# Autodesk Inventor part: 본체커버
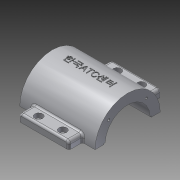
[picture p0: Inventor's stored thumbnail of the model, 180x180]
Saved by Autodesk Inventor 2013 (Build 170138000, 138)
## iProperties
Created: 2015-12
Part Number: 본체커버
Material: 알루미늄 6061
Document SubType Name: Modeling
Designer: mduedu
Density: 2.40731 g/cm^3
Mass: 177.082 g
Surface Area: 200.806 cm^2
Volume: 73.5601 cm^3
Author: mduedu
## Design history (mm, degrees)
sketch "스케치1"
  geometry: L1 (45, 40)-(-45, 40); L2 (-45, 40)-(-45, -40); L3 (-45, -40)-(45, -40); L4 (45, -40)-(45, 40); L5 (45, 40)-(-45, -40); L6 (-45, 40)-(45, -40); 1 further point
  constraints: 12 end point, 2 midpoint, 2 parallel, 1 horizontal, 1 perpendicular
  dimensions: "d0" = 90 distance of L2.end L3.end; "d2" = 80 distance of L1.end L2.end
extrude "돌출1" new body sketch "스케치1" distance "d3" = 10; taper "d4" = 0 deg
sketch "스케치2"
  geometry: L1 (0, 40)-(0, -40) reference; C1 r 32.5 at (80, 0); 1 further point
  constraints: 1 centre point
  dimensions: "d5" = 65 diameter of C1; "d6" = 80 distance from line of C1.centre L1
extrude "돌출2" join sketch "스케치2" stored distance "d7" = 75; taper "d8" = 0 deg
sketch "스케치3"
  geometry: L1 (-27.5, -20)-(27.5, -20); L2 (27.5, -20)-(27.5, 20); L3 (27.5, 20)-(-27.5, 20); L4 (-27.5, 20)-(-27.5, -20); L5 (-27.5, -20)-(27.5, 20); L6 (27.5, -20)-(-27.5, 20); 1 further point
  constraints: 12 end point, 2 midpoint, 2 parallel, 1 horizontal, 1 perpendicular
  dimensions: "d9" = 55 distance of L2.end L3.end; "d11" = 40 distance of L1.end L2.end
extrude "돌출3" new body sketch "스케치3" stored distance "d12" = 75; taper "d13" = 0 deg
fillet "모깎기1"
fillet "모깎기2"
feature "결합1"
  node "솔리드2"
fillet "모깎기3" dims "d14" = 10
sketch "스케치4"
  geometry: L1 (-37.5, 47.5)-(37.5, 47.5) reference; L2 (35, 10)-(45, 10) reference; L3 (32.5, 47.5)-(40, 10); L4 (37.5, 47.5)-(37.5, 112.5) reference; L5 (45, 10)-(45, 0) reference; 1 further point
  constraints: 2 end point, 1 midpoint, 1 point on line
  dimensions: "d15" = 5 distance from line of L3.start L4; "d16" = 5 distance from line of L3.end L5
sketch "스케치5"
  geometry: L1 (10, 40)-(10, 30) reference; L2 (10, 35)-(56.569, 22.522); L3 (0, 40)-(10, 40) reference; 2 further points
  constraints: 2 end point, 1 midpoint, 2 other
  dimensions: "d17" = 5 distance from line of L2.start L3; "d18" = 15 deg angle of L2 L3
feature "리브1" dims "d19" = 1, "d20" = 6, "d21" = 0, "d22" = 0, "d23" = 1, "d24" = 1
feature "리브2" dims "d25" = 1, "d26" = 6, "d27" = 0, "d28" = 0, "d29" = 1, "d30" = 1
fillet "모깎기4" dims "d31" = 2
fillet "모깎기5" dims "d32" = 2
fillet "모깎기6" dims "d33" = 2
sketch "스케치6"
  geometry: A1 r 10 centre (-35, 30) between (-35, 40) and (-45, 30) reference; A2 r 10 centre (35, 30) between (45, 30) and (35, 40) reference; A3 r 10 centre (35, -30) between (35, -40) and (45, -30) reference; A4 r 10 centre (-35, -30) between (-45, -30) and (-35, -40) reference; 5 further points
  constraints: 4 coincident
hole "구멍1" sketch "스케치6" at (-35, 30), (35, 30), (35, -30), (-35, -30) diameter "d34" = 7; stored, may be unused: countersink angle "d38" = 90 deg, drill point angle "d40" = 118 deg; dims "d35" = 6, "d36" = 12, "d37" = 3, "d39" = 8
fillet "모깎기7" dims "d41" = 2
hole "구멍2" diameter "d44" = 45; stored, may be unused: countersink angle "d48" = 90 deg, drill point angle "d50" = 118 deg; dims "d42" = 10, "d43" = 10, "d45" = 6, "d46" = 4, "d47" = 2, "d49" = 8
sketch "스케치7" dims "d52" = 26.5
  geometry: L1 (0, 0)-(32.5, 0); L2 (0, 0)-(22.981, 22.981); A1 r 32.5 centre (0, 0) between (32.5, 0) and (22.981, 22.981) reference; 3 further points
  constraints: 4 end point, 2 point on circle, 1 coincident, 1 horizontal, 1 point on line, 3 other
  dimensions: "d51" = 45 deg angle of L2 L1
hole "구멍3" sketch "스케치7" at (18.738, 18.738) diameter "d54" = 2.459; stored, may be unused: countersink angle "d58" = 90 deg, drill point angle "d60" = 118 deg; dims "d55" = 8, "d56" = 4, "d57" = 2, "d59" = 10
sketch "스케치8"
  geometry: L1 (72.5, 31.623)-(72.5, 46); L2 (72.5, 46)-(87.5, 46); L3 (87.5, 46)-(87.5, 31.623); A1 r 32.5 centre (80, 0) between (87.5, 31.623) and (72.5, 31.623) reference; 2 further points
  constraints: 6 end point, 2 point on circle, 1 midpoint, 1 parallel, 1 vertical, 1 vertical alignment
  dimensions: "d64" = 15 distance of L1.end L2.end; "d66" = 46 distance from line of L2 A1.centre
extrude "돌출4" join sketch "스케치8" stored distance "d67" = 50; taper "d68" = 0 deg
fillet "모깎기8" dims "d69" = 3
fillet "모깎기9" dims "d70" = 2
sketch "스케치13"
  geometry: L1 (-46, 80)-(106, 80); L2 (106, 80)-(106, -30); L3 (106, -30)-(-46, -30); L4 (-46, -30)-(-46, 80); L5 (0, 0)-(60, 0) reference; L6 (76, 75.5)-(76, 84.5) reference; C1 r 32.5 at (30, 80) reference; 1 further point
  constraints: 8 end point, 2 parallel, 1 coincident, 1 horizontal, 1 midpoint, 1 perpendicular
  dimensions: "d99" = 30 distance between parallel lines of L3 L5; "d100" = 30 distance between parallel lines of L2 L6
extrude "돌출8" cut sketch "스케치13" stored distance "d97" = 10; taper "d98" = 0 deg
node "작업 평면2"
sketch "스케치14"
  geometry: 2 further points
  constraints: 1 coincident, 1 other
feature "엠보싱1" sketch "스케치14" dims "d28" = 0, "d102" = 0.5, "d103" = 0
feature "립1" dims "d104" = 1, "d105" = 1.1, "d106" = 0, "d107" = 0, "d108" = 3 deg, "d109" = 0
sketch "스케치15"
  geometry: L1 (-3, -1.039)-(-3, -10.834) reference; L2 (47, -10.834)-(47, -1.039) reference; L3 (-3, -5.936)-(47, -5.936); L4 (-15.5, 65.666)-(-15.5, 0.666) reference; L5 (59.5, 0.666)-(59.5, 65.666) reference; L6 (-15.5, 33.166)-(59.5, 33.166); 5 further points
  constraints: 4 end point, 4 midpoint, 2 point on line, 2 symmetric about line
  dimensions: "d110" = 13 distance from line of point (10, -5.936) L1; "d111" = 13 distance from line of point (34, -5.936) L2
sketch "스케치16"
  geometry: 4 further points
hole "구멍5" sketch "스케치16" at (34, -5.936), (10, 72.269), (34, 72.269), (10, -5.936) diameter "d112" = 4.5; stored, may be unused: countersink angle "d116" = 90 deg, drill point angle "d118" = 0 deg; dims "d113" = 6, "d114" = 8, "d115" = 4.6, "d117" = 8
node "솔리드1"
mirror "대칭1"
mirror "대칭2"
pattern_circular "원형 패턴1" dims angle "d62" = 360 deg
mirror "대칭3"
mirror "대칭4"
